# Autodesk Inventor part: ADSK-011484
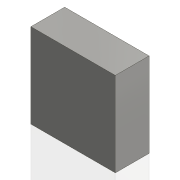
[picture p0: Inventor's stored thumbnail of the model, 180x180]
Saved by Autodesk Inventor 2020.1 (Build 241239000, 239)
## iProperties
Created: 1999-11
Part Number: ADSK-011484
Material: Pearson HRS
Document SubType Name: Modeling
Designer: mpflueger
Density: 7.83 g/cm^3
Appearance: Steel
Mass: 48.9375 g
Surface Area: 22.5 cm^2
Volume: 6.25 cm^3
Control State: 0
Master: False
Checked Out: False
Shininess: 25.0
Length Units: 11269
Angle Units: 11279
Time Units: 11290
Mass Units: 11283
Length Display Precision: 3
Angle Display Precision: 2
Compacted: True
Cutlength: 1
Material Desc: FLAT,HRS,0.375X01.000
Material_Number: A084396
Dimensions: 25x10x25 mm
Mass: 0,049 kg
VLT_Material: Pearson HRS
Density: 7.83
Volumn: 6.145149
Area: 22.580600000000004
PropertySet Name: Model Information
Author: mpflueger
Revision Number: -
Title: ADSK-011484
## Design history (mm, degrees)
node "Solide1"
  node "Extrusion1" dims "d0" = 10, "d1" = 0
sketch "Sketch1"
  geometry: L1 (12.5, -12.5)-(12.5, 12.5); L2 (12.5, 12.5)-(-12.5, 12.5); L3 (-12.5, 12.5)-(-12.5, -12.5); 3 further points; 1 other entity
  constraints: 6 end point, 2 midpoint, 1 horizontal, 1 horizontal alignment, 1 parallel, 1 vertical, 1 vertical alignment, 3 other
  dimensions: "d10" = 25 distance of L1.start L1.end; "d11" = 25 distance of L3.end L1.start (= d10)
node "Corps solides"
node "Corps surfaciques"
